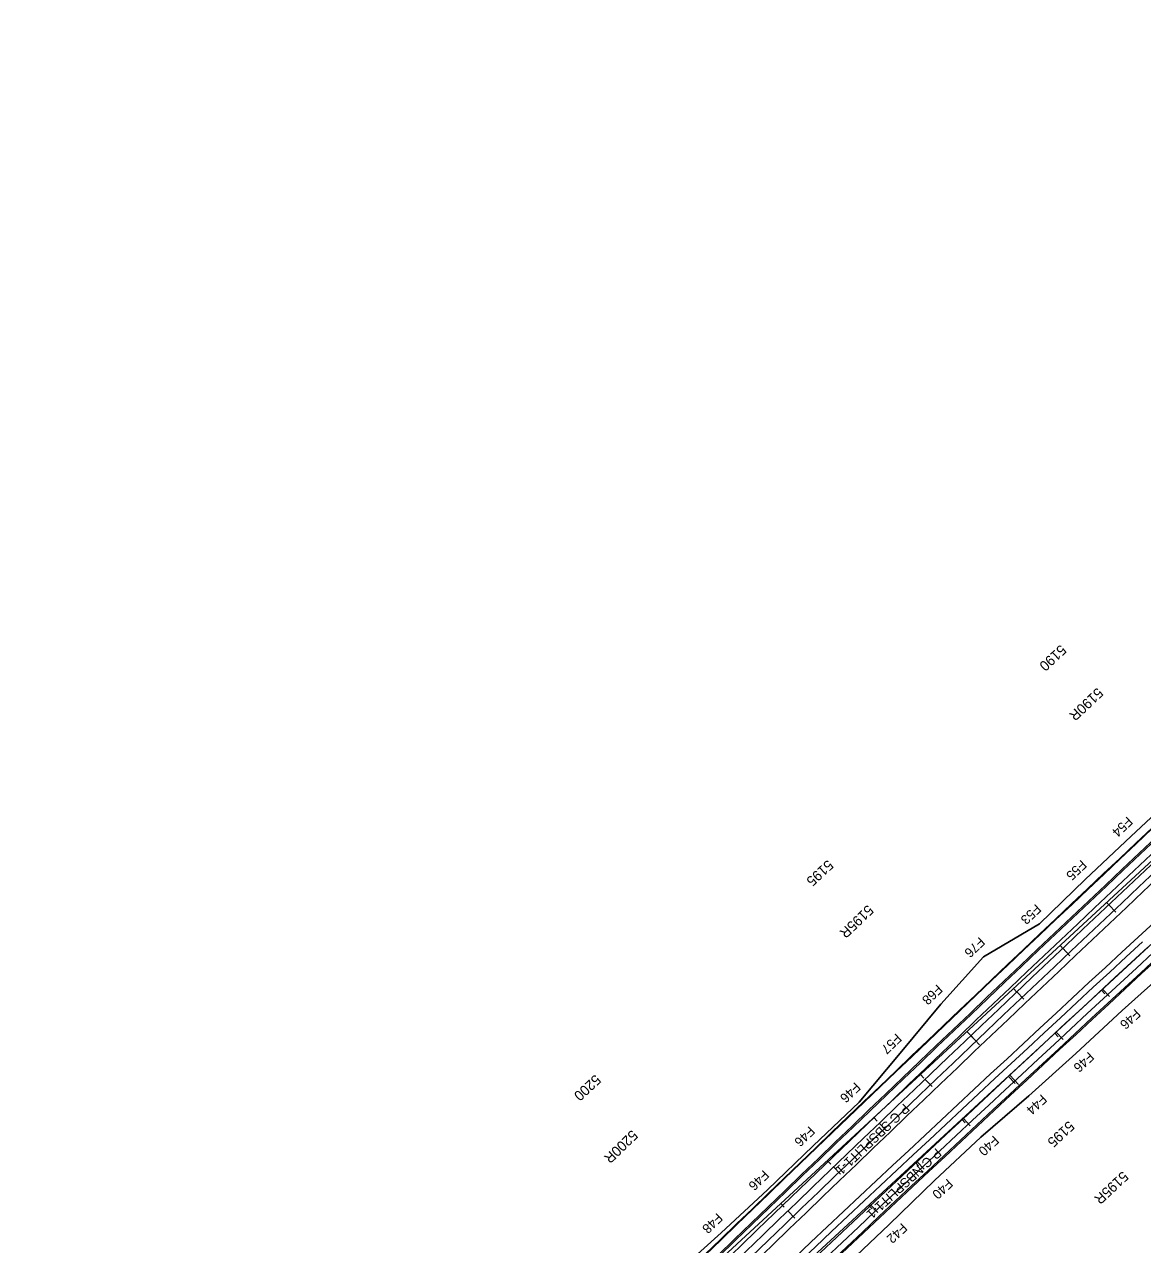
# Model space of a CAD drawing. Extents: x 2160877 to 2175861, y 601747 to 617724.
# Drawn here: x 2168998 to 2170763, y 611849 to 613775 of the extents above; entities that cross this region are included whole.
import ezdxf

# ---------------------------------------------------------------- set-up
doc = ezdxf.new("R2010")
doc.units = 0
for name, color, linetype in [('RD_HC_Cl', 7, 'Continuous'), ('RD_HC_CL_Rel', 7, 'Continuous'), ('RD_HC_Data_Rel', 7, 'Continuous'), ('RD_HC_Data_Tic', 7, 'Continuous'), ('RD_HC_Data_Tic_Rel', 7, 'Continuous'), ('RD_HC_TX_Rel_Sta50', 7, 'Continuous'), ('RD_HC_TX_StaOther', 7, 'Continuous'), ('RD_PD_CstnLmt', 7, 'Continuous'), ('RD_PD_CstnLmt_TX', 7, 'Continuous'), ('RD_PD_Final_LnLine', 7, 'Continuous'), ('RD_PD_Final_TrvlWay', 7, 'Continuous'), ('RD_PD_GR', 7, 'Continuous'), ('RD_PD_MedBWall', 7, 'Continuous')]:
    doc.layers.add(name, color=color, linetype=linetype)

msp = doc.modelspace()

# ---------------------------------------------------------------- linework, layer by layer
at = {"layer": 'RD_HC_Cl'}
for p, q in [((2172207.3, 613775.1), (2163672.2, 605893.8)), ((2172272.5, 613704.6), (2163737.4, 605823.3))]:
    msp.add_line(p, q, dxfattribs=at)
at = {"layer": 'RD_HC_CL_Rel'}
for centre, radius in [((2222221.5, 557873.6), 75000), ((2219616.9, 559421.3), 72000)]:
    msp.add_arc(centre, radius, 132.719474, 134.517591, dxfattribs=at)
at = {"layer": 'RD_HC_Data_Tic'}
for p, q in [((2170706.5, 612389.3), (2170711.9, 612383.4)), ((2170633, 612321.4), (2170638.5, 612315.6)), ((2170559.6, 612253.6), (2170565, 612247.7)), ((2170698.2, 612250.9), (2170703.6, 612245)), ((2170486.1, 612185.8), (2170497, 612174)), ((2170624.7, 612183.1), (2170630.1, 612177.2)), ((2170412.6, 612117.9), (2170418.1, 612112)), ((2170551.2, 612115.2), (2170562.1, 612103.5)), ((2170339.2, 612050.1), (2170344.6, 612044.2)), ((2170477.8, 612047.4), (2170483.2, 612041.5)), ((2170265.7, 611982.2), (2170271.1, 611976.4)), ((2170404.3, 611979.6), (2170409.7, 611973.7)), ((2170192.2, 611914.4), (2170197.7, 611908.5)), ((2170330.8, 611911.7), (2170336.3, 611905.8))]:
    msp.add_line(p, q, dxfattribs=at)
at = {"layer": 'RD_HC_Data_Tic_Rel'}
for p, q in [((2170709.9, 612385.6), (2170720.9, 612374)), ((2170637.3, 612316.9), (2170648.3, 612305.3)), ((2170564.7, 612248.1), (2170575.7, 612236.5)), ((2170700.1, 612252.6), (2170711, 612240.9)), ((2170492.3, 612179.2), (2170506.1, 612164.7)), ((2170626.8, 612184.6), (2170637.7, 612172.9)), ((2170553.6, 612116.5), (2170567.2, 612101.9)), ((2170419.9, 612110.1), (2170431, 612098.6)), ((2170347.6, 612041), (2170358.7, 612029.5)), ((2170480.4, 612048.4), (2170491.3, 612036.7)), ((2170407.4, 611980.1), (2170418.3, 611968.4)), ((2170275.5, 611971.8), (2170286.5, 611960.3)), ((2170203.4, 611902.5), (2170214.5, 611891)), ((2170334.4, 611911.7), (2170345.4, 611900))]:
    msp.add_line(p, q, dxfattribs=at)
at = {"layer": 'RD_PD_CstnLmt'}
for p, q in [((2170818.5, 612562.2), (2170745.3, 612493.8)), ((2170745.3, 612493.8), (2170672.5, 612425.3)), ((2170672.5, 612425.3), (2170600.7, 612355.5)), ((2170600.7, 612355.5), (2170512, 612303.6)), ((2170512, 612303.6), (2170445.1, 612228.7)), ((2170805.7, 612285.7), (2170731.3, 612218.9)), ((2170445.1, 612228.7), (2170380.6, 612151.3)), ((2170731.3, 612218.9), (2170658, 612151)), ((2170380.6, 612151.3), (2170315.7, 612074.3)), ((2170658, 612151), (2170583.7, 612084.2)), ((2170315.7, 612074.3), (2170243.6, 612005)), ((2170583.7, 612084.2), (2170507.8, 612019)), ((2170507.8, 612019), (2170434.9, 611950.6)), ((2170243.6, 612005), (2170171.3, 611935.8)), ((2170434.9, 611950.6), (2170363.2, 611881)), ((2170171.3, 611935.8), (2170097.9, 611867.7)), ((2170363.2, 611881), (2170290.7, 611812.3)), ((2170097.9, 611867.7), (2170023.5, 611800.8))]:
    msp.add_line(p, q, dxfattribs=at)
at = {"layer": 'RD_PD_Final_LnLine'}
for centre, radius in [((2222221.5, 557873.6), 75012), ((2222221.5, 557873.6), 74988), ((2219616.9, 559421.3), 72012), ((2219616.9, 559421.3), 71988)]:
    msp.add_arc(centre, radius, 132.719474, 134.517591, dxfattribs=at)
at = {"layer": 'RD_PD_Final_TrvlWay'}
msp.add_line((2172257.5, 613720.8), (2170756.5, 612334.7), dxfattribs=at)
for centre, radius in [((2222220.1, 557875.1), 75024.3), ((2222220.1, 557875.1), 75022), ((2222221.5, 557873.6), 74978), ((2219616.9, 559421.3), 72022), ((2219616.9, 559421.3), 71978)]:
    msp.add_arc(centre, radius, 132.719474, 134.517591, dxfattribs=at)
at = {"layer": 'RD_PD_GR'}
msp.add_arc((2219616.9, 559421.3), 71976, 132.719474, 134.517591, dxfattribs=at)
at = {"layer": 'RD_PD_MedBWall'}
for radius, end in [(75039.3, 134.421287), (75038.3, 134.421298)]:
    msp.add_arc((2222220.1, 557875.1), radius, 132.719474, end, dxfattribs=at)

# ---------------------------------------------------------------- texts
at = {"layer": 'RD_HC_Data_Rel'}
for s, rotation, p in [('P C SBSPLIT1-1', 223.5528, (2170386.8, 612072.9)), ('P C NBSPLIT1-1', 222.7536, (2170437.4, 612002.5))]:
    msp.add_text(s, height=15, rotation=rotation, dxfattribs=at).set_placement(p)
at = {"layer": 'RD_HC_TX_Rel_Sta50'}
for s, rotation, p in [('5190R', 223.2262, (2170691.9, 612729.3)), ('5195R', 223.6082, (2170329.4, 612386.5)), ('5200R', 223.9901, (2169957.2, 612031.3)), ('5195R', 222.9559, (2170731.8, 611966.1))]:
    msp.add_text(s, height=16, rotation=rotation, dxfattribs=at).set_placement(p)
at = {"layer": 'RD_HC_TX_StaOther'}
for s, p in [('5190', (2170633.9, 612797.1)), ('5195', (2170266.2, 612457.5)), ('5200', (2169899.3, 612118.7)), ('5195', (2170646.7, 612045.5))]:
    msp.add_text(s, height=16, rotation=222.7195, dxfattribs=at).set_placement(p)
at = {"layer": 'RD_PD_CstnLmt_TX'}
for s, rotation, p in [('F54', 223.3026, (2170739.1, 612525.9)), ('F55', 223.379, (2170666.4, 612457.5)), ('F53', 223.4554, (2170594.6, 612387.8)), ('F76', 223.5318, (2170505.8, 612335.7)), ('F68', 223.6082, (2170438.9, 612261)), ('F46', 222.7968, (2170751.6, 612222.3)), ('F57', 223.6845, (2170374.3, 612183.5)), ('F46', 222.8764, (2170678.2, 612154.4)), ('F46', 223.7609, (2170309.4, 612106.5)), ('F44', 222.9559, (2170603.8, 612087.5)), ('F46', 223.8373, (2170237.3, 612037.2)), ('F40', 223.0355, (2170528.1, 612022.5)), ('F46', 223.9137, (2170164.9, 611968)), ('F40', 223.1151, (2170455.2, 611954.2)), ('F48', 223.9901, (2170091.7, 611900.1)), ('F42', 223.1947, (2170383.3, 611884.4))]:
    msp.add_text(s, height=15, rotation=rotation, dxfattribs=at).set_placement(p)

doc.saveas('drawing.dxf')
